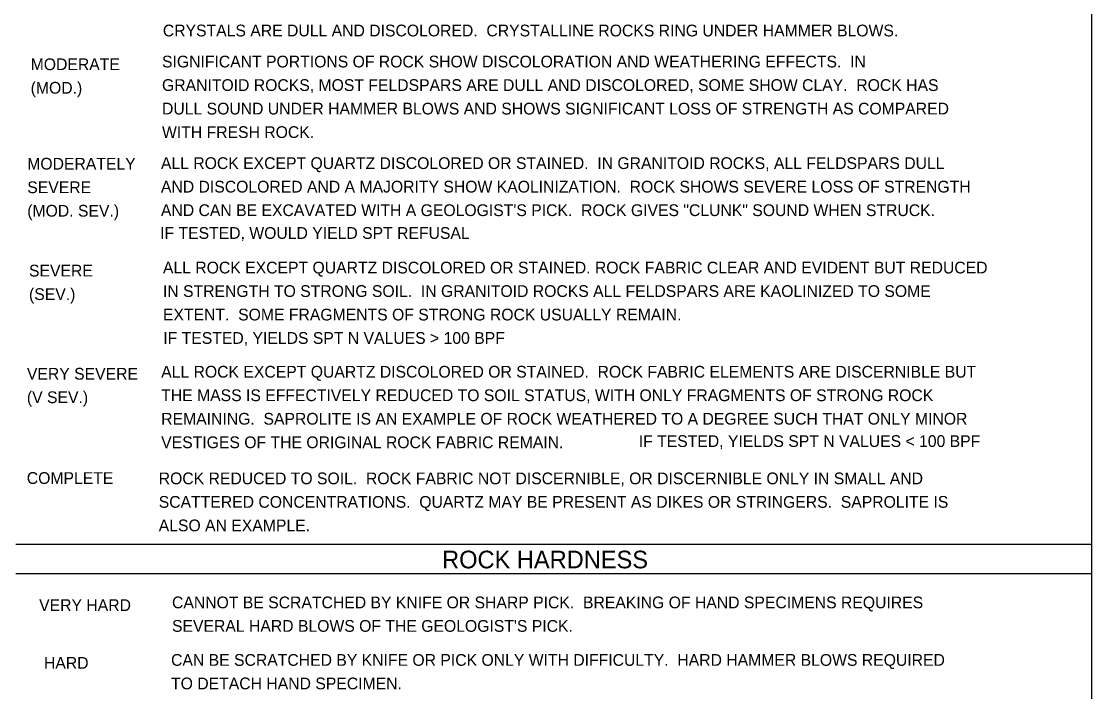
# Model space of a CAD drawing. Extents: x 278710 to 279187, y 171464 to 171625.
# Drawn here: x 279081.88 to 279121.33, y 171516.98 to 171541.71 of the extents above; entities that cross this region are included whole.
import ezdxf

# ---------------------------------------------------------------- set-up
doc = ezdxf.new("R2010")
doc.units = 0
doc.layers.add('Prop Strc Sect_ Misc - User Comment (Tx - small)', color=7, linetype='Continuous')

msp = doc.modelspace()

# ---------------------------------------------------------------- linework, layer by layer
at = {"layer": 'Prop Strc Sect_ Misc - User Comment (Tx - small)'}
for p, q in [((279121.332, 171566.02), (279121.332, 171485.806)), ((279081.678, 171522.419), (279121.332, 171522.419)), ((279081.678, 171521.334), (279121.332, 171521.334))]:
    msp.add_line(p, q, dxfattribs=at)

# ---------------------------------------------------------------- texts
for s, height, p in [('CRYSTALS ARE DULL AND DISCOLORED.  CRYSTALLINE ROCKS RING UNDER HAMMER BLOWS.', 0.43381, (279087.097, 171541.155)), ('SIGNIFICANT PORTIONS OF ROCK SHOW DISCOLORATION AND WEATHERING EFFECTS.  IN ', 0.43381, (279087.066, 171540.01)), ('MODERATE', 0.4338, (279082.225, 171539.91)), ('GRANITOID ROCKS, MOST FELDSPARS ARE DULL AND DISCOLORED, SOME SHOW CLAY.  ROCK HAS ', 0.43381, (279087.066, 171539.142)), ('(MOD.)', 0.4338, (279082.225, 171539.042)), ('DULL SOUND UNDER HAMMER BLOWS AND SHOWS SIGNIFICANT LOSS OF STRENGTH AS COMPARED ', 0.43381, (279087.066, 171538.274)), ('WITH FRESH ROCK.', 0.43381, (279087.066, 171537.407)), ('MODERATELY', 0.4338, (279082.099, 171536.24)), ('ALL ROCK EXCEPT QUARTZ DISCOLORED OR STAINED.  IN GRANITOID ROCKS, ALL FELDSPARS DULL ', 0.43381, (279087.027, 171536.262)), ('SEVERE', 0.4338, (279082.099, 171535.372)), ('AND DISCOLORED AND A MAJORITY SHOW KAOLINIZATION.  ROCK SHOWS SEVERE LOSS OF STRENGTH ', 0.43381, (279087.027, 171535.394)), ('(MOD. SEV.)', 0.43381, (279082.099, 171534.505)), ('AND CAN BE EXCAVATED WITH A GEOLOGIST\'S PICK.  ROCK GIVES "CLUNK" SOUND WHEN STRUCK.', 0.43381, (279087.027, 171534.526)), ('IF TESTED, WOULD YIELD SPT REFUSAL', 0.43381, (279086.997, 171533.685)), ('SEVERE', 0.4338, (279082.164, 171532.297)), ('ALL ROCK EXCEPT QUARTZ DISCOLORED OR STAINED. ROCK FABRIC CLEAR AND EVIDENT BUT REDUCED ', 0.43381, (279087.101, 171532.409)), ('(SEV.)', 0.4338, (279082.164, 171531.429)), ('IN STRENGTH TO STRONG SOIL.  IN GRANITOID ROCKS ALL FELDSPARS ARE KAOLINIZED TO SOME ', 0.43381, (279087.101, 171531.542)), ('EXTENT.  SOME FRAGMENTS OF STRONG ROCK USUALLY REMAIN.', 0.43381, (279087.101, 171530.675)), ('IF TESTED, YIELDS SPT N VALUES > 100 BPF', 0.43381, (279087.114, 171529.811)), ('VERY SEVERE', 0.43381, (279082.086, 171528.492)), ('ALL ROCK EXCEPT QUARTZ DISCOLORED OR STAINED.  ROCK FABRIC ELEMENTS ARE DISCERNIBLE BUT ', 0.43381, (279087.036, 171528.566)), ('THE MASS IS EFFECTIVELY REDUCED TO SOIL STATUS, WITH ONLY FRAGMENTS OF STRONG ROCK ', 0.43381, (279087.036, 171527.698)), ('(V SEV.)', 0.4338, (279082.086, 171527.625)), ('REMAINING.  SAPROLITE IS AN EXAMPLE OF ROCK WEATHERED TO A DEGREE SUCH THAT ONLY MINOR ', 0.43381, (279087.036, 171526.831)), ('VESTIGES OF THE ORIGINAL ROCK FABRIC REMAIN.', 0.43381, (279087.036, 171525.963)), ('IF TESTED, YIELDS SPT N VALUES < 100 BPF', 0.43381, (279104.64, 171526.007)), ('COMPLETE', 0.4338, (279082.082, 171524.644)), ('ROCK REDUCED TO SOIL.  ROCK FABRIC NOT DISCERNIBLE, OR DISCERNIBLE ONLY IN SMALL AND ', 0.43381, (279086.945, 171524.631)), ('SCATTERED CONCENTRATIONS.  QUARTZ MAY BE PRESENT AS DIKES OR STRINGERS.  SAPROLITE IS ', 0.43381, (279086.945, 171523.764)), ('ALSO AN EXAMPLE.', 0.43381, (279086.945, 171522.896)), ('ROCK HARDNESS', 0.6507, (279097.391, 171521.53)), ('VERY HARD', 0.4338, (279082.537, 171519.955)), ('CANNOT BE SCRATCHED BY KNIFE OR SHARP PICK.  BREAKING OF HAND SPECIMENS REQUIRES ', 0.43381, (279087.435, 171520.055)), ("SEVERAL HARD BLOWS OF THE GEOLOGIST'S PICK.", 0.43381, (279087.435, 171519.188)), ('CAN BE SCRATCHED BY KNIFE OR PICK ONLY WITH DIFFICULTY.  HARD HAMMER BLOWS REQUIRED ', 0.43381, (279087.4, 171517.933)), ('HARD', 0.4338, (279082.715, 171517.825)), ('TO DETACH HAND SPECIMEN.', 0.43381, (279087.4, 171517.066))]:
    msp.add_text(s, height=height, dxfattribs=at).set_placement(p)

doc.saveas('drawing.dxf')
